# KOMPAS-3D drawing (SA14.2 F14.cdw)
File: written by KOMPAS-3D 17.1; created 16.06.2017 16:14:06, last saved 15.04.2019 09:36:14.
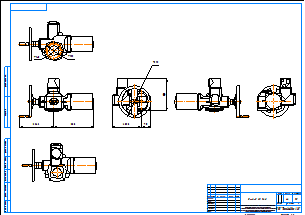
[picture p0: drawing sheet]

Sheet 1: A2, landscape

Title block, sheet 1: name: Привод SA 14.2; material: Сталь 20  ГОСТ 1050-88; mass: 44; sheets: 1; sheet format: A2; stored path: \\adlc.lan\data\АДЛ_ПКД\3D-модели\Поставщики\Сервоприводы AUMA\Электроприводы серии SA\KOMPAS 2D\SA 14.2 F14.cdw

Views: Спереди 1, Проекционный вид 2, Проекционный вид 3, Проекционный вид 4, Проекционный вид 5, Проекционный вид 6
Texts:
  Klimkovich
  ADL
  Рама для чертежей
  Лит-Масса-Масштаб
  Материал-Предприятие
  Масштаб
  Изм.
  Лист
  № докум.
  Подп.
  Дата
  Лит.
  Разраб.
  Пров.
  Т.контр.
  Листов
  Внимание! Данный продукт является объектом авторского права ООО «Торговый Дом АДЛ».
  Запрещается изменение, копирование, распространение
  (в том числе путем копирования на другие сайты и ресурсы в Интернете)
  или любое иное использование информации и объектов без предварительного
  согласия правообладателя (ООО «Торговый Дом АДЛ»).
  Н.контр.
  Утв.
  ООО "Торговый дом АДЛ"
  Изменение
  Номер документа
  Подпись
  Обозначение документа
  Наименование изделия
  Масса изделия по ГОСТ 2.109-73
  Порядковый номер листа
  Общее количество листов в документе
  Характер работы, выполненной лицом, подписавшим документ
  Наименование или индекс предприятия, выпускающего документ
  Инв. № подл.
  Подп. и дата
  Взам. инв. №
  Инв. № дубл.
  Инвентарный номер подлинника по ГОСТ 2.501-68
  Подпись принявшего подлинник в отдел технической документации
  Инвентарный номер подлинника, взамен которого выпущен данный подлинник
  Инвентарный номер дубликата по ГОСТ 2.502-68
  Подпись принявшего дубликат в отдел технической документации
  Справ. №
  Перв. примен.
  Обозначение документа, взамен или на основании которого выпущен данный документ
  Обозначение документа, в котором впервые записан данный документ
  Подпись лица, копировавшего чертеж
  Обозначение формата листа
  !Рама для чертежа
Dimensions and other numbers on the sheet: 315; 316; 90; 285,8; 155; 140; 336,3; 388; 1:5; 1; 44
